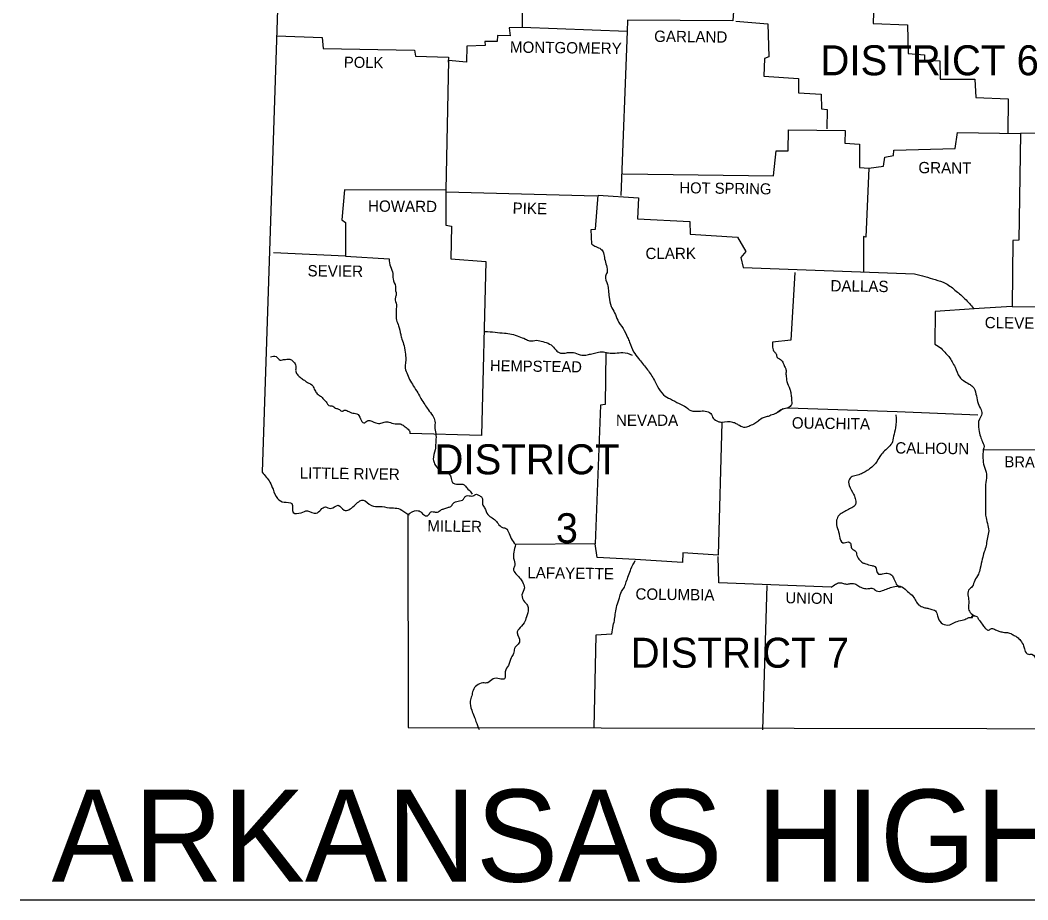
# Model space of a CAD drawing. Extents: x 191 to 3403, y 68 to 2102.
# Drawn here: x 2625.2 to 2999.8, y 1369.4 to 1696.4 of the extents above; entities that cross this region are included whole.
import ezdxf

# ---------------------------------------------------------------- set-up
doc = ezdxf.new("R2010")
doc.units = 0
for name, color, linetype in [('1', 7, 'Continuous'), ('2', 7, 'Continuous'), ('3', 7, 'Continuous')]:
    doc.layers.add(name, color=color, linetype=linetype)

msp = doc.modelspace()

# ---------------------------------------------------------------- linework, layer by layer
at = {"layer": '1'}
msp.add_line((2625.16, 1369.37), (3289.7, 1369.37), dxfattribs=at)
for points in [[(2703.71, 1956.42), (2723.96, 1793.81), (2715.15, 1528.37)], [(2812.02, 1750.86), (2811.82, 1693.62), (2806.93, 1693.52), (2807.32, 1690.59), (2802.62, 1690.68), (2802.53, 1688.53), (2797.93, 1688.53), (2798.03, 1686.97), (2791.18, 1686.77), (2791.08, 1680.8), (2784.43, 1681.39), (2783.35, 1633.25), (2745.68, 1633.35), (2744.8, 1622.19), (2746.17, 1621.22), (2746.07, 1608.69), (2719.36, 1609.87)], [(2922.97, 1707.81), (2890.97, 1708.78), (2890.09, 1696.16), (2850.96, 1696.36), (2850.76, 1692.15)], [(2931.68, 1708.1), (2942.63, 1707.41), (2942.24, 1695.18), (2955.06, 1694.69), (2955.26, 1684.03), (2961.32, 1683.54), (2961.32, 1681.68), (2967, 1681.29), (2967.19, 1674.44), (2980.11, 1674.44), (2980.5, 1667.69), (2992.44, 1667.1), (2992.34, 1654.38)], [(2850.76, 1692.15), (2811.82, 1693.62)], [(2891.27, 1695.97), (2903.11, 1695.09), (2903.5, 1682.76), (2901.83, 1682.17), (2901.64, 1675.62), (2914.46, 1674.74), (2914.46, 1669.35), (2922.97, 1668.86), (2923.07, 1663.48), (2925.12, 1663.19), (2925.02, 1655.95)], [(2720.54, 1690.59), (2737.46, 1690), (2737.85, 1685.89), (2771.71, 1685.2), (2772.1, 1683.05), (2784.43, 1682.66), (2784.33, 1680.8)], [(2850.76, 1692.15), (2848.51, 1631.2)], [(3109.06, 1665.64), (3072.08, 1666.61), (3071.88, 1654.58), (2997.03, 1654.29)], [(2849.2, 1639.32), (2905.16, 1638.53), (2906.24, 1647.83), (2910.64, 1647.83), (2910.74, 1655.66), (2931.87, 1655.36), (2931.68, 1650.67), (2937.16, 1650.27), (2937.16, 1641.66), (2940.68, 1641.37)], [(2940.68, 1641.37), (2946.16, 1642.15), (2946.55, 1645.48), (2949.78, 1646.07), (2949.97, 1648.02), (2972.77, 1648.71), (2973.65, 1654.68), (2997.03, 1654.29)], [(2997.03, 1654.09), (2996.45, 1614.56), (2994.2, 1614.47), (2993.9, 1589.91)], [(2940.68, 1641.37), (2939.5, 1615.74), (2938.62, 1616.03), (2938.72, 1602.72)], [(2783.35, 1633.25), (2783.35, 1620.24), (2785.5, 1619.85), (2785.31, 1607.71), (2798.22, 1606.74), (2796.66, 1542.06), (2770.04, 1542.75)], [(2783.55, 1632.57), (2839.51, 1631.1)], [(2837.65, 1613.19), (2837.46, 1618.57), (2839.02, 1618.67), (2840, 1631.29), (2855.07, 1630.32), (2854.68, 1622.59), (2874.15, 1621.51), (2874.24, 1616.81), (2891.85, 1615.74), (2894.89, 1610.45), (2893.03, 1608.11), (2893.91, 1604.49), (2957.7, 1602.14)], [(2746.07, 1608.69), (2762.31, 1607.71)], [(2913.09, 1602.63), (2911.62, 1577.48), (2904.87, 1576.7)], [(2979.81, 1589.03), (2965.33, 1588.15), (2965.24, 1575.92)], [(2993.9, 1589.91), (2979.62, 1589.03)], [(2993.9, 1589.91), (3028.54, 1589.71)], [(2842.84, 1572.98), (2842.64, 1553.51), (2840.88, 1553.31), (2838.92, 1501.75)], [(2910.64, 1552.34), (2951.15, 1550.87), (2981.18, 1549.69)], [(2885.98, 1546.86), (2884.71, 1497.55), (2871.5, 1498.43), (2871.41, 1494.81), (2853.79, 1495.88)], [(2983.14, 1536.68), (3027.36, 1536.78)], [(2769.26, 1512.61), (2769.46, 1433.46), (3128.04, 1432.87)], [(2853.79, 1495.88), (2839.61, 1496.67), (2838.92, 1501.75), (2809.28, 1501.46)], [(2926.69, 1485.61), (2884.91, 1487.17), (2884.71, 1497.06)], [(2902.72, 1486.29), (2901.15, 1432.58)], [(2845.18, 1468.19), (2839.12, 1467.8), (2838.43, 1433.36)]]:
    msp.add_lwpolyline(points, dxfattribs=at)
for points in [[(2837.65, 1613.19), (2839.22, 1612.21), (2841.08, 1611.33), (2842.05, 1609.87), (2842.45, 1607.62), (2843.13, 1605.17), (2843.33, 1602.63), (2842.74, 1601.26), (2843.52, 1598.13), (2843.82, 1595.97), (2844.11, 1593.43), (2844.89, 1590.01), (2846.16, 1587.66), (2847.34, 1584.82), (2849.29, 1581.79), (2850.96, 1578.46), (2851.74, 1576.7), (2853.21, 1573.08), (2855.07, 1570.63), (2858, 1566.91), (2860.64, 1563.1), (2862.11, 1560.26), (2864.36, 1557.13), (2866.91, 1555.57), (2870.13, 1553.9), (2872.19, 1552.92), (2874.54, 1551.26), (2877.57, 1551.06), (2879.82, 1551.06), (2881.88, 1550.18), (2882.85, 1548.42), (2884.61, 1547.25), (2885.98, 1546.86)], [(2762.31, 1607.71), (2762.8, 1604.78), (2763.68, 1602.24), (2763.78, 1600.28), (2764.66, 1597.34), (2764.66, 1596.27), (2764.96, 1594.11), (2764.56, 1592.94), (2765.05, 1590.59), (2764.96, 1588.83), (2764.96, 1587.36), (2765.05, 1584.92), (2765.84, 1582.76), (2766.62, 1579.54), (2767.11, 1577.87), (2767.89, 1575.33), (2768.38, 1572.2), (2768.48, 1569.85), (2768.28, 1567.7), (2768.87, 1565.25), (2769.95, 1562.81), (2771.32, 1560.46), (2772.98, 1557.82), (2774.15, 1555.76), (2775.62, 1553.51), (2776.79, 1551.65), (2778.56, 1549.3), (2779.34, 1547.35), (2779.34, 1544.61), (2779.73, 1542.06), (2779.63, 1539.23), (2779.44, 1536.68), (2778.75, 1533.16), (2779.24, 1531.5), (2781.1, 1529.05), (2782.27, 1528.37), (2784.33, 1527.97), (2785.31, 1526.6), (2785.89, 1524.55), (2787.95, 1523.86), (2790.2, 1523.67), (2791.27, 1522.49), (2792.74, 1520.93), (2793.23, 1520.15)], [(2957.7, 1602.14), (2965.33, 1599.98), (2969.25, 1598.52), (2973.16, 1595.68), (2976.39, 1592.84), (2979.62, 1589.22)], [(2798.03, 1580.71), (2801.74, 1580.42), (2805.17, 1580.03), (2807.81, 1579.73), (2810.55, 1578.75), (2813, 1577.87), (2814.56, 1577.19), (2817.2, 1577.38), (2819.45, 1576.89), (2822, 1576.01), (2823.86, 1574.35), (2825.03, 1573.08), (2827.28, 1572.59), (2829.14, 1572.88), (2831.39, 1572.69), (2833.93, 1571.9), (2835.99, 1572), (2837.65, 1572.39), (2839.61, 1572.88), (2842.05, 1573.08), (2843.91, 1572.69), (2846.36, 1572.59), (2849.2, 1572.88), (2852.72, 1571.9)], [(2904.87, 1576.7), (2904.87, 1574.84), (2905.55, 1573.08), (2906.24, 1572.3), (2906.53, 1571.02), (2907.41, 1570.44), (2908.68, 1569.26), (2909.37, 1567.6), (2909.86, 1566.52), (2909.86, 1565.15), (2909.96, 1563.78), (2910.15, 1562.12), (2911.33, 1559.19), (2911.62, 1558.01), (2911.81, 1557.03), (2911.91, 1555.37), (2911.91, 1553.41), (2910.64, 1552.34)], [(2965.24, 1575.92), (2967.49, 1574.45), (2969.34, 1572.49), (2970.71, 1571.02), (2971.59, 1569.36), (2972.77, 1567.4), (2974.43, 1563.69), (2975.9, 1562.41), (2977.95, 1561.14), (2979.23, 1560.26), (2980.5, 1557.42), (2981.09, 1554.59), (2982.16, 1552.04), (2982.65, 1550.09), (2981.77, 1548.13), (2981.57, 1544.22), (2982.16, 1541.57), (2982.94, 1539.62), (2983.43, 1537.37), (2983.14, 1536.68)], [(2718.19, 1571.22), (2720.34, 1571.32), (2721.81, 1570.05), (2722.69, 1570.14), (2724.25, 1570.34), (2725.72, 1570.24), (2726.8, 1569.36), (2727.68, 1567.8), (2727.58, 1566.33), (2727.68, 1565.74), (2728.36, 1564.47), (2729.54, 1563.49), (2730.81, 1562.51), (2731.98, 1561.73), (2733.94, 1560.46), (2734.14, 1560.07), (2734.92, 1558.5), (2735.9, 1557.23), (2737.07, 1556.45), (2738.34, 1555.08), (2738.93, 1554.49), (2739.91, 1553.12), (2740.98, 1553.02), (2742.45, 1552.14), (2743.53, 1551.85), (2744.7, 1551.06), (2745.88, 1551.46), (2747.34, 1550.87), (2749.3, 1550.28), (2750.38, 1550.09), (2751.65, 1548.23), (2752.92, 1546.66), (2754.49, 1547.54), (2757.42, 1546.66), (2759.28, 1546.56), (2760.94, 1547.05), (2762.22, 1546.96), (2764.56, 1546.37), (2766.03, 1546.37), (2767.6, 1545.78), (2769.06, 1544.61), (2770.04, 1543.34), (2770.04, 1542.75)], [(2908.78, 1551.95), (2906.24, 1550.28), (2904.28, 1549.5), (2902.81, 1549.01), (2901.44, 1548.62), (2899.68, 1547.44), (2898.31, 1546.47), (2896.45, 1545.59), (2894.69, 1545), (2892.54, 1545.68), (2891.37, 1546.37), (2890.09, 1546.86), (2885.98, 1546.86)], [(2906.24, 1550.28), (2908.78, 1551.95), (2910.64, 1552.34)], [(2950.75, 1549.69), (2950.56, 1544.8), (2949.87, 1541.77), (2949.19, 1539.03), (2947.72, 1537.46), (2946.16, 1535.9), (2944.69, 1534.14), (2943.42, 1531.99), (2942.14, 1530.62), (2940.48, 1529.25), (2938.82, 1528.27), (2936.96, 1527.39), (2934.9, 1526.9), (2933.44, 1525.82), (2933.34, 1523.47), (2935, 1520.15), (2935.59, 1518.58), (2935.79, 1516.72), (2935.1, 1515.65), (2933.53, 1514.77), (2931.68, 1513.69), (2930.01, 1512.71), (2928.84, 1511.05), (2928.64, 1508.8), (2929.43, 1506.16), (2929.72, 1504.59), (2930.99, 1502.14), (2931.97, 1502.24), (2933.73, 1502.14), (2933.93, 1501.65), (2934.02, 1501.17), (2934.42, 1499.89), (2935.88, 1498.82), (2936.08, 1497.84), (2936.96, 1495.98), (2938.43, 1494.71), (2939.5, 1494.32), (2941.75, 1493.63), (2942.93, 1493.34), (2944.2, 1490.5), (2945.77, 1490.6), (2946.94, 1490.79), (2948.9, 1490.31), (2949.78, 1489.13), (2950.66, 1487.17), (2951.83, 1485.8), (2952.61, 1485.8)], [(2983.14, 1536.68), (2983.53, 1530.62), (2984.41, 1527.68), (2984.12, 1524.55), (2984.02, 1521.52), (2984.02, 1518.78), (2984.02, 1516.14), (2984.02, 1513.4), (2984.22, 1511.44), (2984.9, 1508.6), (2985.19, 1505.96), (2984.61, 1503.42), (2984.31, 1501.07), (2983.53, 1498.72), (2982.85, 1496.08), (2982.06, 1492.65), (2981.38, 1490.4), (2980.01, 1488.06), (2979.13, 1485.9), (2977.76, 1484.53), (2977.56, 1482.18), (2977.86, 1480.03), (2977.66, 1478.08), (2978.35, 1476.22), (2980.11, 1474.94)], [(2715.15, 1528.37), (2717.99, 1524.65), (2719.17, 1522.01), (2720.83, 1518.58), (2723.28, 1517.21), (2726.11, 1516.72), (2726.7, 1513.4), (2729.63, 1513.3), (2731.98, 1513.98), (2735.21, 1513.1), (2738.64, 1515.45), (2740.59, 1514.86), (2743.43, 1516.04), (2745.58, 1514.28), (2749.3, 1515.84), (2752.63, 1517.99), (2755.76, 1515.94), (2758.79, 1515.65), (2762.41, 1515.16), (2765.25, 1514.96), (2767.79, 1513.69), (2769.65, 1512.42), (2769.26, 1512.61)], [(2769.26, 1512.61), (2772.68, 1514.08), (2774.15, 1513.59), (2775.42, 1512.32), (2776.89, 1512.32), (2777.67, 1513.49), (2779.14, 1513.59), (2780.32, 1513.49), (2781.59, 1514.28), (2782.66, 1514.77), (2784.13, 1515.25), (2785.21, 1515.65), (2786.19, 1516.72), (2787.95, 1517.6), (2790, 1518.29), (2790.59, 1519.27), (2791.57, 1519.66), (2793.52, 1519.56), (2794.8, 1520.15), (2795.87, 1519.66), (2796.85, 1518.97), (2797.05, 1516.43), (2797.83, 1515.06), (2799, 1512.61), (2800.67, 1511.34), (2802.23, 1510.07), (2802.82, 1509.29), (2804.48, 1507.82), (2805.95, 1507.33), (2806.64, 1506.25), (2807.71, 1503.71), (2809.28, 1501.46)], [(2809.28, 1501.46), (2808.69, 1498.62), (2808.59, 1496.37), (2809.08, 1493.73), (2808.59, 1492.46), (2809.38, 1490.6), (2810.84, 1489.13), (2811.92, 1487.57), (2812.6, 1485.32), (2811.72, 1482.77), (2812.7, 1480.13), (2813.58, 1479.15), (2814.07, 1477.59), (2813.39, 1474.55), (2812.51, 1472.3), (2810.55, 1470.05), (2809.96, 1468.98), (2810.26, 1467.51), (2810.74, 1465.16), (2810.26, 1464.48), (2808.98, 1462.81), (2808.59, 1460.95), (2807.71, 1459.39), (2806.73, 1456.55), (2805.46, 1454.2), (2805.27, 1451.56), (2803.31, 1451.56), (2801.06, 1451.56), (2799, 1450.09), (2797.15, 1450), (2794.89, 1449.11), (2793.52, 1447.26), (2793.04, 1445.2), (2792.45, 1443.24), (2793.04, 1439.92), (2793.92, 1437.57), (2794.6, 1435.71), (2795.78, 1432.68)], [(2845.18, 1468.19), (2845.67, 1471.32), (2846.16, 1473.77), (2846.46, 1476.12), (2847.04, 1478.76), (2847.92, 1481.6), (2848.71, 1483.95), (2849.78, 1485.61), (2850.47, 1487.57), (2851.35, 1489.91), (2852.23, 1492.36), (2853.79, 1495.49)], [(2926.69, 1485.61), (2928.25, 1486.69), (2929.72, 1487.27), (2931.19, 1486.98), (2932.75, 1486.78), (2934.12, 1486.98), (2935.88, 1486.69), (2937.35, 1485.8), (2939.01, 1485.12), (2940.68, 1485.12), (2942.14, 1485.12), (2943.42, 1484.24), (2945.77, 1484.34), (2947.72, 1485.12), (2949.68, 1485.71), (2952.32, 1486), (2954.67, 1484.34), (2956.33, 1482.97), (2957.7, 1481.4), (2958.68, 1479.64), (2959.76, 1478.66), (2961.52, 1477.98), (2962.89, 1477.68), (2964.55, 1477.19), (2965.43, 1476.8), (2966.21, 1474.94), (2967.49, 1472.4), (2969.93, 1471.52), (2972.96, 1472.69), (2975.41, 1473.38), (2977.17, 1473.97), (2978.25, 1474.36), (2979.23, 1474.46), (2978.93, 1474.65), (2980.11, 1474.94), (2981.18, 1474.16), (2981.87, 1473.09), (2983.04, 1471.52), (2984.12, 1470.15), (2985.19, 1469.66), (2986.27, 1470.25), (2987.74, 1469.76), (2989.01, 1469.27), (2990.48, 1468.88), (2991.75, 1468.78), (2993.41, 1468.39), (2994.69, 1467.7), (2995.86, 1467.02), (2997.03, 1465.75), (2998.21, 1463.79), (2998.6, 1462.23), (2999.97, 1460.66), (3001.24, 1460.66), (3003.1, 1458.12), (3003.78, 1457.14), (3005.25, 1455.38), (3006.33, 1455.38), (3008.38, 1454.98)]]:
    msp.add_spline(points, degree=3, dxfattribs=at)

# ---------------------------------------------------------------- texts
at = {"layer": '2'}
for s, height, rotation, p in [('GARLAND', 4.207, 359.3658, (2860.84, 1688.33)), ('MONTGOMERY', 4.207, 359.2944, (2807.22, 1684.32)), ('POLK', 4.108, 359.2152, (2745.49, 1678.75)), ('GRANT', 4.207, 359.4032, (2959.07, 1639.51)), ('HOT SPRING', 4.109, 359.2216, (2870.23, 1632.08)), ('HOWARD', 4.207, 359.5145, (2754.49, 1625.23)), ('PIKE', 4.206, 359.0452, (2808.2, 1624.44)), ('SEVIER', 4.207, 359.4271, (2731.98, 1601.16)), ('DALLAS', 4.206, 359.2462, (2926.39, 1595.58)), ('CLEVELAND', 4.207, 359.3377, (2983.73, 1581.88)), ('HEMPSTEAD', 4.108, 359.1885, (2799.79, 1565.94)), ('OUACHITA', 4.207, 359.2043, (2912.01, 1544.61)), ('CALHOUN', 4.207, 359.3634, (2950.46, 1535.31)), ('BRADLEY', 4.108, 359.1449, (2991.07, 1530.22)), ('LITTLE RIVER', 4.2073, 359.1697, (2729.05, 1526.02)), ('MILLER', 4.206, 359.1319, (2776.5, 1506.35)), ('LAFAYETTE', 4.206, 359.1839, (2813.68, 1488.94)), ('COLUMBIA', 4.206, 359.2125, (2853.89, 1481.01)), ('UNION', 4.109, 358.9584, (2909.66, 1479.64))]:
    msp.add_text(s, height=height, rotation=rotation, dxfattribs=at).set_placement(p)
for s, height, p in [('CLARK', 4.207, (2857.63, 1607.59)), ('NEVADA', 4.207, (2846.65, 1545.59)), ('ARKANSAS HIGHWAY DISTRICT 10', 34.244, (2636.86, 1376.13))]:
    msp.add_text(s, height=height, dxfattribs=at).set_placement(p)
at = {"layer": '3'}
for s, height, p in [('DISTRICT 6', 11.154, (2922.67, 1675.91)), ('DISTRICT', 11.154, (2779.19, 1527.57)), ('3', 11.06, (2824.3, 1502.04)), ('DISTRICT 7', 11.154, (2852.13, 1455.67))]:
    msp.add_text(s, height=height, dxfattribs=at).set_placement(p)

doc.saveas('drawing.dxf')
